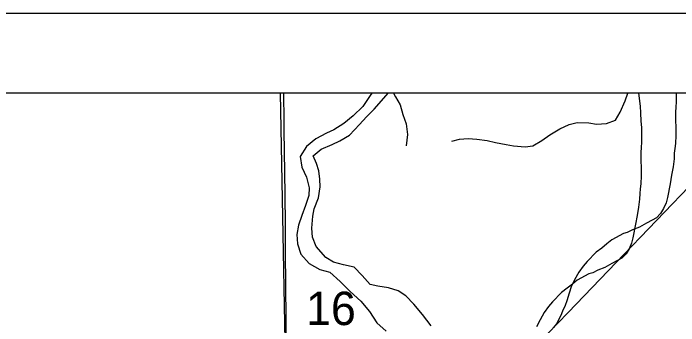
# Model space of a CAD drawing. Extents: x -21.1 to 50.3, y -4.9 to 22.1.
# Drawn here: x 7.565 to 8.398, y 20.608 to 21 of the extents above; entities that cross this region are included whole.
import ezdxf

# ---------------------------------------------------------------- set-up
doc = ezdxf.new("R2010")
doc.units = 0
for name, color, linetype in [('GM_X_Corporation', 7, 'Continuous'), ('GM_X_County', 7, 'Continuous'), ('GM_X_County_Road', 7, 'Continuous'), ('GM_X_Major_Lake', 7, 'Continuous'), ('GM_X_Major_River', 7, 'Continuous'), ('GM_X_Minor_River', 7, 'Continuous'), ('GM_X_Rail_Line_Text', 7, 'Continuous'), ('GM_X_Section_Text', 7, 'Continuous'), ('GM_X_State_Route', 7, 'Continuous'), ('SH_Cut_Line', 7, 'Continuous'), ('SH_Data', 7, 'Continuous')]:
    doc.layers.add(name, color=color, linetype=linetype)

msp = doc.modelspace()

# ---------------------------------------------------------------- linework, layer by layer
at = {"layer": 'GM_X_Corporation'}
msp.add_lwpolyline([(7.89976, 20.9), (6.88768, 20.9), (6.89298, 20.43015), (6.89867, 20.4302), (7.90835, 20.43439)], close=True, dxfattribs=at)
at = {"layer": 'GM_X_County'}
msp.add_lwpolyline([(8.9, 14.74638), (8.9, 20.9), (2.1, 20.9), (2.1, 14.1), (8.89319, 14.1)], dxfattribs=at)
at = {"layer": 'GM_X_County_Road'}
msp.add_lwpolyline([(7.90983, 20.43411), (7.90938, 20.44431), (7.90886, 20.46588), (7.90857, 20.48164), (7.90828, 20.50961), (7.90776, 20.55283), (7.90684, 20.61158), (7.90654, 20.63017), (7.90624, 20.64567), (7.9062, 20.6705), (7.90609, 20.68911), (7.90592, 20.72617), (7.90589, 20.73065), (7.90587, 20.73542), (7.90538, 20.77251), (7.90493, 20.80036), (7.90414, 20.85304), (7.90409, 20.86415), (7.90403, 20.87799), (7.90387, 20.88657), (7.90364, 20.89901), (7.90362, 20.9)], dxfattribs=at)
at = {"layer": 'GM_X_Major_Lake'}
for points in [[(8.01401, 20.9), (8.01203, 20.8968), (8.00254, 20.88314), (7.99079, 20.87139), (7.97903, 20.8619), (7.96651, 20.85394), (7.95704, 20.84977), (7.94376, 20.84256), (7.93201, 20.83308), (7.92442, 20.82056), (7.92631, 20.80729), (7.93199, 20.79477), (7.93539, 20.78112), (7.93501, 20.77164), (7.93083, 20.75912), (7.92628, 20.74661), (7.9221, 20.73447), (7.9202, 20.72271), (7.92095, 20.71096), (7.92511, 20.69806), (7.93572, 20.6863), (7.94898, 20.67872), (7.96149, 20.67531), (7.97437, 20.66393), (7.98687, 20.65142), (8.00013, 20.63929), (8.01112, 20.62601), (8.02021, 20.61198), (8.03195, 20.60136)], [(8.08844, 20.6082), (8.07745, 20.62223), (8.06647, 20.6355), (8.05662, 20.64574), (8.04714, 20.65219), (8.03464, 20.65598), (8.02137, 20.65787), (8.0119, 20.66015), (8.00205, 20.67114), (7.99182, 20.68176), (7.97855, 20.68479), (7.96604, 20.68821), (7.95657, 20.69389), (7.94445, 20.70754), (7.93953, 20.7193), (7.93877, 20.73068), (7.9403, 20.74547), (7.94182, 20.75495), (7.94714, 20.7686), (7.94942, 20.78264), (7.94904, 20.79212), (7.94753, 20.80236), (7.94451, 20.81184), (7.94034, 20.82132), (7.95058, 20.82966), (7.96423, 20.83535), (7.97371, 20.83991), (7.98622, 20.84711), (7.99836, 20.86039), (8.00746, 20.87025), (8.01695, 20.87973), (8.02908, 20.89377), (8.03433, 20.9)]]:
    msp.add_lwpolyline(points, dxfattribs=at)
at = {"layer": 'GM_X_Major_River'}
for points in [[(8.01401, 20.9), (8.01203, 20.8968), (8.00254, 20.88314), (7.99079, 20.87139), (7.97903, 20.8619), (7.96651, 20.85394), (7.95704, 20.84977), (7.94376, 20.84256), (7.93201, 20.83308), (7.92442, 20.82056), (7.92631, 20.80729), (7.93199, 20.79477), (7.93539, 20.78112), (7.93501, 20.77164), (7.93083, 20.75912), (7.92628, 20.74661), (7.9221, 20.73447), (7.9202, 20.72271), (7.92095, 20.71096), (7.92511, 20.69806), (7.93572, 20.6863), (7.94898, 20.67872), (7.96149, 20.67531), (7.97437, 20.66393), (7.98687, 20.65142), (8.00013, 20.63929), (8.01112, 20.62601), (8.02021, 20.61198), (8.03195, 20.60136)], [(8.08844, 20.6082), (8.07745, 20.62223), (8.06647, 20.6355), (8.05662, 20.64574), (8.04714, 20.65219), (8.03464, 20.65598), (8.02137, 20.65787), (8.0119, 20.66015), (8.00205, 20.67114), (7.99182, 20.68176), (7.97855, 20.68479), (7.96604, 20.68821), (7.95657, 20.69389), (7.94445, 20.70754), (7.93953, 20.7193), (7.93877, 20.73068), (7.9403, 20.74547), (7.94182, 20.75495), (7.94714, 20.7686), (7.94942, 20.78264), (7.94904, 20.79212), (7.94753, 20.80236), (7.94451, 20.81184), (7.94034, 20.82132), (7.95058, 20.82966), (7.96423, 20.83535), (7.97371, 20.83991), (7.98622, 20.84711), (7.99836, 20.86039), (8.00746, 20.87025), (8.01695, 20.87973), (8.02908, 20.89377), (8.03433, 20.9)]]:
    msp.add_lwpolyline(points, dxfattribs=at)
at = {"layer": 'GM_X_Minor_River'}
for points in [[(8.04107, 20.9), (8.04372, 20.89532), (8.04926, 20.88536), (8.05287, 20.87314), (8.05687, 20.86131), (8.05856, 20.84798), (8.05682, 20.83395)], [(8.11402, 20.83969), (8.12382, 20.8422), (8.13478, 20.84322), (8.14541, 20.84233), (8.15834, 20.84036), (8.169, 20.83796), (8.18194, 20.83561), (8.19145, 20.83394), (8.20588, 20.83276), (8.2157, 20.83376), (8.22692, 20.84047), (8.23698, 20.84754), (8.24931, 20.85504), (8.26093, 20.86063), (8.2711, 20.86315), (8.28551, 20.86273), (8.2954, 20.86107), (8.30788, 20.86175), (8.31915, 20.86619), (8.32498, 20.87619), (8.33109, 20.89038), (8.33456, 20.9)], [(8.34785, 20.9), (8.34985, 20.88368), (8.35027, 20.87532), (8.35071, 20.86469), (8.35152, 20.85672), (8.35162, 20.83848), (8.35128, 20.83164), (8.35093, 20.82556), (8.3511, 20.79631), (8.35077, 20.78605), (8.35004, 20.77997), (8.34931, 20.77427), (8.34897, 20.76705), (8.34789, 20.75716), (8.34604, 20.74651), (8.3442, 20.73549), (8.34087, 20.71837), (8.339, 20.7119), (8.336, 20.70467), (8.33223, 20.69857), (8.32692, 20.69322), (8.32161, 20.69015), (8.3144, 20.68632), (8.30567, 20.68133), (8.29694, 20.67786), (8.29049, 20.67479), (8.28555, 20.67324), (8.27112, 20.66556), (8.26506, 20.66059), (8.25862, 20.65523), (8.25142, 20.64988), (8.24006, 20.63842), (8.23515, 20.63231), (8.22986, 20.62506), (8.22458, 20.61554), (8.22006, 20.60677)], [(8.39485, 20.9), (8.39491, 20.889), (8.39457, 20.88216), (8.39422, 20.87608), (8.39438, 20.84683), (8.39406, 20.83657), (8.39333, 20.83048), (8.3926, 20.82478), (8.39226, 20.81756), (8.39118, 20.80768), (8.38933, 20.79703), (8.38749, 20.786), (8.38416, 20.76889), (8.38229, 20.76242), (8.37929, 20.75519), (8.37551, 20.74909), (8.37021, 20.74374), (8.3649, 20.74067), (8.35769, 20.73683), (8.34896, 20.73184), (8.34023, 20.72838), (8.33377, 20.7253), (8.32883, 20.72376), (8.31441, 20.71608), (8.30835, 20.71111), (8.30191, 20.70575), (8.2947, 20.70039), (8.28335, 20.68893), (8.27843, 20.68283), (8.27315, 20.67558), (8.26787, 20.66605), (8.26335, 20.65729), (8.26111, 20.6493), (8.25812, 20.63941), (8.25587, 20.6337), (8.25248, 20.62646), (8.25061, 20.62113), (8.24797, 20.61655), (8.24572, 20.61123), (8.24118, 20.60588)]]:
    msp.add_lwpolyline(points, dxfattribs=at)
at = {"layer": 'GM_X_Rail_Line_Text'}
msp.add_lwpolyline([(8.9, 20.9), (2.80139, 20.9)], dxfattribs=at)
at = {"layer": 'GM_X_State_Route'}
msp.add_lwpolyline([(8.06383, 20.43445), (8.07832, 20.44799), (8.1172, 20.48343), (8.16937, 20.53193), (8.18904, 20.55111), (8.20828, 20.57124), (8.23389, 20.59837), (8.25989, 20.62502), (8.31974, 20.68745), (8.42091, 20.79269), (8.42581, 20.79765)], dxfattribs=at)
at = {"layer": 'SH_Cut_Line'}
msp.add_lwpolyline([(8.9, 16.40522), (8.9, 20.9), (2.1, 20.9)], dxfattribs=at)
at = {"layer": 'SH_Data'}
msp.add_line((2, 21), (9, 21), dxfattribs=at)

# ---------------------------------------------------------------- texts
at = {"layer": 'GM_X_Section_Text'}
msp.add_text('16', height=0.041856, rotation=0.00001, dxfattribs=at).set_placement((7.93169, 20.60914))

doc.saveas('drawing.dxf')
